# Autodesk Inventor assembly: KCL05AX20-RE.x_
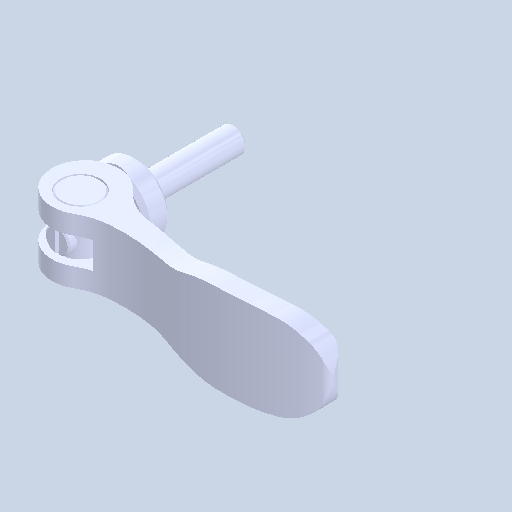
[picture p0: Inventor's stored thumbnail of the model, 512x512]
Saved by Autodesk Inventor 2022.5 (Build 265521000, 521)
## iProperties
Created: 2024-08
Part Number: KCL05AX20-RE.x_
Document SubType Name: Assembly
Designer: ImaoCorp
Author: ImaoCorp
Sending System: SOLIDWORKS 2022-2022290
MC: AMD64
MC_MODEL: Intel64 Family 6 Model 60 Stepping 3, GenuineIntel
OS: Windows_NT
FRU: Parasolid Version 33.1, build 260,  4-25-2022
FORMAT: text
GUISE: transmit
KEY: FILEKCL05AX20-RE.x_t
DATE: Thu Aug 29 10:48:27 2024
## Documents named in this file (5)
- Y:\5.更新分\2024年対応\1001_KCL\データ\kcl05ax20-re\KCL05AX20-RE.x_.iam
- Y:\5.更新分\2024年対応\1001_KCL\データ\kcl05ax20-re\KCL05AX20-RE_01.ipt
- Y:\5.更新分\2024年対応\1001_KCL\データ\kcl05ax20-re\KCL05AX20-RE_02.ipt
- Y:\5.更新分\2024年対応\1001_KCL\データ\kcl05ax20-re\KCL05AX20-RE_03.ipt
- Y:\5.更新分\2024年対応\1001_KCL\データ\kcl05ax20-re\KCL05AX20-RE_04.ipt
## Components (4 placed, 4 different names)
1. KCL05AX20-RE_01
2. KCL05AX20-RE_02
3. KCL05AX20-RE_03
4. KCL05AX20-RE_04
